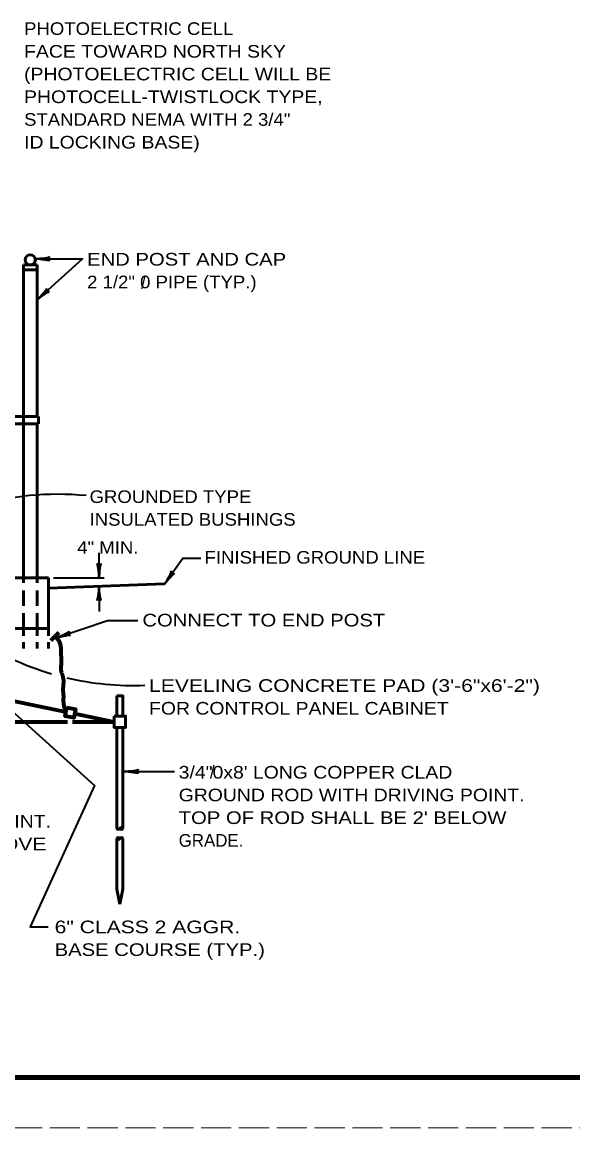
# Model space of a CAD drawing. Extents: x -1 to 679, y 0 to 440.
# Drawn here: x 262.1 to 371.3, y -0.1 to 219 of the extents above; entities that cross this region are included whole.
import ezdxf

# ---------------------------------------------------------------- set-up
doc = ezdxf.new("R2010")
doc.units = 0
for name, pattern in [('LONG_DASHED', [7.5, 6, -1.5]), ('MEDIUM_DASHED', [4.5, 3, -1.5]), ('SHORT_DASHED', [2.7, 1.5, -1.2])]:
    doc.linetypes.add(name, pattern=pattern)
doc.layers.add('1', color=7, linetype='Continuous', lineweight=53)
doc.layers.add('61', color=7, linetype='Continuous', lineweight=35)

msp = doc.modelspace()

# ---------------------------------------------------------------- linework, layer by layer
at = {"layer": '1'}
for p, q in [((262.349, 170.858), (265.099, 170.858)), ((262.349, 140.858), (262.349, 170.858)), ((265.099, 140.858), (265.099, 170.858)), ((262.349, 169.858), (265.099, 169.858)), ((209.947, 140.858), (265.349, 140.858)), ((262.349, 140.608), (262.349, 139.608)), ((265.349, 140.858), (265.349, 139.358)), ((209.947, 139.358), (265.349, 139.358)), ((262.349, 108.858), (262.349, 139.358)), ((265.099, 108.858), (265.099, 139.358)), ((267.349, 98.858), (267.349, 108.858)), ((267.349, 106.858), (290.335, 107.66)), ((243.197, 98.858), (267.349, 98.858)), ((280.849, 81.483), (280.849, 85.483)), ((280.849, 79.233), (280.849, 59.233)), ((282.099, 79.233), (282.099, 59.233)), ((280.849, 57.233), (280.849, 47.233)), ((282.099, 57.233), (282.099, 47.233)), ((280.849, 47.233), (281.474, 44.233)), ((282.099, 47.233), (281.474, 44.233))]:
    msp.add_line(p, q, dxfattribs=at)
at = {"layer": '1', "lineweight": 35}
for p, q in [((277.349, 108.858), (277.349, 113.858)), ((268.349, 108.858), (278.349, 108.858)), ((277.349, 107.242), (277.349, 102.242)), ((282.284, 70.513), (292.303, 70.513))]:
    msp.add_line(p, q, dxfattribs=at)
at = {"layer": '1', "linetype": 'MEDIUM_DASHED'}
for p, q in [((262.349, 98.858), (262.349, 108.858)), ((265.099, 98.858), (265.099, 108.858))]:
    msp.add_line(p, q, dxfattribs=at)
at = {"layer": '1', "linetype": 'SHORT_DASHED'}
for p, q in [((262.349, 98.858), (262.349, 94.858)), ((265.099, 98.858), (265.099, 94.858)), ((267.349, 98.858), (267.349, 94.858))]:
    msp.add_line(p, q, dxfattribs=at)
at = {"layer": '1', "lineweight": 70}
for p, q in [((269.391, 98.069), (267.811, 96.462)), ((256.099, 85.4), (270.803, 82.342)), ((272.517, 81.986), (280.349, 80.358)), ((256.099, 80.358), (271.099, 80.358)), ((272.099, 80.358), (280.349, 80.358))]:
    msp.add_line(p, q, dxfattribs=at)
at = {"layer": '1', "lineweight": 35}
for points in [[(264.699, 172.081), (274.091, 172.038), (265.099, 163.969)], [(290.335, 107.66), (293.977, 112.769), (297.51, 112.769)], [(268.862, 96.972), (279.041, 100.443), (285.012, 100.443)], [(246.145, 95.098), (276.46, 67.771), (263.701, 39.759), (267.297, 39.759)]]:
    msp.add_lwpolyline(points, dxfattribs=at)
at = {"layer": '1'}
for points in [[(267.349, 108.858), (245.349, 108.858), (245.349, 109.858), (193.349, 109.858), (193.349, 108.858), (189.849, 108.858), (189.849, 109.858), (138.849, 109.858), (138.849, 108.858)], [(282.099, 81.483), (282.099, 85.483), (280.849, 85.483)]]:
    msp.add_lwpolyline(points, dxfattribs=at)
at = {"layer": '1', "lineweight": 70}
msp.add_lwpolyline([(270.981, 83.199), (272.695, 82.843), (272.339, 81.129), (270.625, 81.486)], close=True, dxfattribs=at)
at = {"layer": '1'}
msp.add_lwpolyline([(280.349, 81.483), (282.599, 81.483), (282.599, 79.233), (280.349, 79.233)], close=True, dxfattribs=at)
msp.add_circle((263.724, 171.858), 1, dxfattribs=at)
at = {"layer": '1', "lineweight": 35}
for centre, radius, start, end in [((269.132, 68.061), 57.373, 84.36386, 129.06474), ((284.153, 145.103), 57.546, 219.03891, 253.64268), ((284.153, 145.103), 57.546, 256.72245, 272.24824)]:
    msp.add_arc(centre, radius, start, end, dxfattribs=at)
at = {"layer": '1'}
for centre, start, end in [((281.162, 59.413), 209.9406, 330.0594), ((281.787, 59.053), 29.9406, 150.0594), ((281.787, 59.413), 209.9406, 330.0594), ((281.162, 57.053), 29.9406, 150.0594), ((281.162, 57.413), 209.9406, 330.0594), ((281.787, 57.053), 29.9406, 150.0594)]:
    msp.add_arc(centre, 0.361, start, end, dxfattribs=at)
at = {"layer": '1', "lineweight": 40}
for centre, major_axis, ratio, start_param, end_param in [((265.819, 171.864), (-1.756, 0.184), 0.07063, 3.1407148, 5.41811), ((265.819, 171.864), (-1.756, 0.184), 0.07063, 3.1407148, 5.41811), ((265.792, 172.352), (-1.786, -0.148), 0.122415, 0.8963533, 3.1415927), ((265.792, 172.352), (-1.786, -0.148), 0.122415, 0.8963533, 3.1415927), ((265.727, 164.903), (-1.225, -1.309), 0.122415, 0.8963533, 3.1415927), ((265.727, 164.903), (-1.225, -1.309), 0.122415, 0.8963533, 3.1415927), ((266.074, 164.559), (1.425, 1.042), 0.07063, 6.2823074, 8.5597026), ((266.074, 164.559), (1.425, 1.042), 0.07063, 6.2823074, 8.5597026), ((277.073, 109.949), (0.156, -1.786), 0.122415, 0.8963533, 3.1415927), ((277.073, 109.949), (0.156, -1.786), 0.122415, 0.8963533, 3.1415927), ((277.561, 109.978), (-0.176, -1.756), 0.07063, 3.1407148, 5.41811), ((277.561, 109.978), (-0.176, -1.756), 0.07063, 3.1407148, 5.41811), ((290.744, 108.709), (-0.909, -1.545), 0.122415, 0.8963533, 3.1415927), ((291.158, 108.45), (-1.163, -1.328), 0.07063, 3.1407148, 5.41811), ((277.138, 106.121), (0.176, 1.756), 0.07063, 3.1407148, 5.41811), ((277.138, 106.121), (0.176, 1.756), 0.07063, 3.1407148, 5.41811), ((277.626, 106.151), (-0.156, 1.786), 0.122415, 0.8963533, 3.1415927), ((277.626, 106.151), (-0.156, 1.786), 0.122415, 0.8963533, 3.1415927), ((269.806, 97.585), (-1.64, -0.724), 0.122415, 0.8963533, 3.1415927), ((269.806, 97.585), (-1.64, -0.724), 0.122415, 0.8963533, 3.1415927), ((269.991, 97.133), (-1.719, -0.401), 0.07063, 3.1407148, 5.41811), ((269.991, 97.133), (-1.719, -0.401), 0.07063, 3.1407148, 5.41811), ((283.404, 70.301), (-1.756, 0.176), 0.07063, 3.1407148, 5.41811), ((283.404, 70.301), (-1.756, 0.176), 0.07063, 3.1407148, 5.41811), ((283.375, 70.789), (-1.786, -0.156), 0.122415, 0.8963533, 3.1415927), ((283.375, 70.789), (-1.786, -0.156), 0.122415, 0.8963533, 3.1415927)]:
    msp.add_ellipse(centre, major_axis=major_axis, ratio=ratio, start_param=start_param, end_param=end_param, dxfattribs=at)
at = {"layer": '1', "lineweight": 70}
msp.add_spline([(270.803, 82.342), (270.317, 84.584), (270.344, 85.455), (270.262, 86.409), (270.317, 87.58), (270.344, 88.615), (270.126, 89.678), (269.908, 90.305), (269.854, 91.367), (269.935, 92.784), (269.854, 93.846), (269.663, 95.889), (268.655, 97.251)], degree=3, dxfattribs=at)
at = {"layer": '61', "lineweight": 158}
msp.add_line((667.629, 9.921), (28.569, 9.941), dxfattribs=at)
at = {"layer": '61', "linetype": 'LONG_DASHED', "lineweight": 13}
msp.add_line((678.569, -0.059), (-1.491, -0.079), dxfattribs=at)

# ---------------------------------------------------------------- texts
at = {"layer": '1'}
for s, width, p in [('PHOTOELECTRIC CELL', 1.1, (262.493, 216.42)), ('FACE TOWARD NORTH SKY', 1.15, (262.493, 211.92)), ('(PHOTOELECTRIC CELL WILL BE', 1.15, (262.493, 207.42)), ('PHOTOCELL-TWISTLOCK TYPE,', 1.15, (262.493, 202.92)), ('STANDARD NEMA WITH 2 3/4"', 1.1, (262.493, 198.42)), ('ID LOCKING BASE)', 1.15, (262.493, 193.92)), ('END POST AND CAP', 1.2, (274.984, 170.731)), ('2 1/2" 0 PIPE (TYP.)', 1.1, (274.984, 166.231)), ('GROUNDED TYPE', 1.1, (275.468, 123.703)), ('INSULATED BUSHINGS', 1.1, (275.468, 119.203)), ('4" MIN.', 1.1, (273.029, 113.641)), ('FINISHED GROUND LINE', 1.1, (298.267, 111.689)), ('CONNECT TO END POST', 1.2, (285.953, 99.249)), ('LEVELING CONCRETE PAD (3\'-6"x6\'-2")', 1.25, (287.266, 86.29)), ('FOR CONTROL PANEL CABINET', 1.15, (287.266, 81.79)), ('3/4"0x8\' LONG COPPER CLAD', 1.15, (293.144, 69.115)), ('GROUND ROD WITH DRIVING POINT.', 1.15, (293.144, 64.615)), ('GROUND ROD WITH DRIVING POINT.', 1.15, (199.264, 59.411)), ("TOP OF ROD SHALL BE 2' BELOW", 1.2, (293.144, 60.115)), ('TOP OF ROD SHALL BE 4" ABOVE', 1.25, (199.264, 54.911)), ('6" CLASS 2 AGGR.', 1.25, (268.549, 38.478)), ('BASE COURSE (TYP.)', 1.2, (268.549, 33.978))]:
    msp.add_text(s, height=2.5, dxfattribs=dict(at, width=width)).set_placement(p)
for s, p in [('/', (285.697, 166.158)), ('/', (299.331, 69.139)), ('GRADE.', (293.144, 55.615))]:
    msp.add_text(s, height=2.5, dxfattribs=at).set_placement(p)

doc.saveas('drawing.dxf')
